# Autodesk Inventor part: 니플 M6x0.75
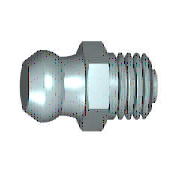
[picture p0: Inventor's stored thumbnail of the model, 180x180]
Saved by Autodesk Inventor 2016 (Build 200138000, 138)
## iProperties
IsCustomPart: 1
Created: 2012-02
Part Number: 니플 M6x0.75
Material: 강철, 연강
Description: 윤활 니플, 원추 유형 A
Document SubType Name: Modeling
Standard: JIS B 1575
Designer: mduedu
Standards Organization: JIS
Language: ko-KR
Size Designation: MT 6 x 0.75
Categories: <MemberInstance><Categories><Category DisplayName="기타 부품" InternalName="5aa15e00-363f-49f2-933f-16f664388e3f" Mnemonic="OTHER"><Category DisplayName="그리스 부속품" I
Density: 1 g/cm^3
Appearance: 강철
Author: mduedu
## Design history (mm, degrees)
sketch "스케치1"
  geometry: L1 (-8.8, 0)-(-8.8, 2.4); L2 (-8.8, 2.4)-(-7.335, 3.202); L3 (-8.8, 0)-(4.7, 0); L4 (4.7, 0)-(4.7, 1.5); L5 (4.7, 1.5)-(4, 1.5); L6 (4, 1.5)-(4, 3); L7 (4, 3)-(0, 3); L8 (-11.5, 0)-(7.4, 0) reference; L9 (0, -1.733)-(0, 10.398) reference; L10 (-3, 3.5)-(0, 3.5); L11 (0, 3.5)-(0, 3); A1 r 3.3 centre (-6.535, 0) between (-4.789, 2.8) and (-7.335, 3.202); A2 r 6 centre (-6.053, 8.665) between (-4.789, 2.8) and (-3, 3.5)
  constraints: 18 end point, 5 perpendicular, 4 point on circle, 2 centre point, 2 parallel, 2 point on line, 1 collinear, 1 vertical
  dimensions: "d0" = 13.5 distance between parallel lines of L1 L4 (= GL); "d1" = 5.6 diameter of A1.start L3 (= KGB2); "d2" = 0.7 distance between parallel lines of L4 L6 (= PHH); "d3" = 3 diameter of L5 L3 (= 0.5 x NND); "d4" = 6 diameter of L7 L3 (= NND); "d5" = 6.6 dimension on A1 L3 (= KR); "d6" = 4.8 diameter of L1.end L3 (= KGB1); "d7" = 6 radius of A2 (= RBN); "d11" = 7 diameter of L10.start L3 (= SW); "d14" = 3 distance of L10.start L10.end (= KOH); "d15" = 4 distance between parallel lines of L6 L11 (= NLG); "d61" = 7.33505 distance from line of L9 L2.end (computed from KGB1, KR, PHH, GL, NLG, VERS); "d62" = 6.53505 distance from line of L9 A1.centre (computed from NLG, GL, PHH, KR, KGB1)
revolve "본체" sketch "스케치1" stored, may be unused: angle "d25" = 90 deg
sketch "스케치2"
  geometry: L1 (2.021, 3.5)-(4.041, 0); L2 (4.041, 0)-(2.021, -3.5); L3 (2.021, -3.5)-(-2.021, -3.5); L4 (-2.021, -3.5)-(-4.041, 0); L5 (-4.041, 0)-(-2.021, 3.5); L6 (-2.021, 3.5)-(2.021, 3.5); C1 r 3.5 at (0, 0) reference; 1 further point
  constraints: 12 end point, 1 coincident, 1 horizontal, 1 tangent, 11 other
extrude "머리" join sketch "스케치2" distance "d17" = 3 (= KOH); taper "d18" = 0 deg
sketch "스케치3"
  geometry: L1 (2.687, 4.041)-(3, 4.041); L2 (3, 4.041)-(3, 3.5); L3 (3, 3.5)-(2.687, 4.041); L4 (0.313, 4.041)-(0, 4.041); L5 (0, 4.041)-(0, 3.5); L6 (0, 3.5)-(0.313, 4.041); L7 (3.6, 0)-(-0.6, 0) reference; L8 (0, 4.041)-(0, 2.021) reference; L9 (0, 4.041)-(3, 4.041) reference; L10 (3, 3.031)-(3, 4.041) reference
  constraints: 12 end point, 4 collinear, 3 perpendicular, 1 horizontal
  dimensions: "d19" = 3.5 distance from line of L5.end L7 (= 0.5 x SW); "d20" = 3.5 distance from line of L2.end L7 (= 0.5 x SW); "d21" = 30 deg angle of L6 L5; "d22" = 30 deg angle of L2 L3
revolve "모따기1" sketch "스케치3" stored, may be unused: angle "d56" = 90 deg
body "Solid1"
fillet "모깎기1" dims "d8" = 0.2 (= RR)
feature "스레드1" dims "d9" = 3.53991 (= NLG - GAL), "d10" = 0
chamfer "모따기2" distance "d23" = 0.46009 (= -0.5 x GD1 + 0.5 x NND); stored, may be unused: angle "d24" = 45 deg, second distance "d59" = 0.46009 (= -0.5 x GD1 + 0.5 x NND)
other parameters: "NLG" = 4 [user parameter; used in 4 equation terms], "GL" = 13.5 [user parameter; used in 3 equation terms], "NND" = 6 [user parameter; used in 4 equation terms], "KGB1" = 4.8 [user parameter; used in 3 equation terms], "KGB2" = 5.6 [user parameter; used in 1 equation term], "VERS" = 0.8 [user parameter; used in 1 equation term], "KR" = 6.6 [user parameter; used in 3 equation terms], "RBN" = 6 [user parameter; used in 1 equation term], "SW" = 7 [user parameter; used in 3 equation terms], "KOH" = 3 [user parameter; used in 2 equation terms], "GAL" = 0.46009 (= 0.61345 x PTC) [user parameter; used in 1 equation term], "FAWI" = 45 deg [user parameter], "PHH" = 0.7 [user parameter; used in 3 equation terms], "GD1" = 5.07983 (= THREADDIA - 1.2269 x PTC) [user parameter; used in 2 equation terms], "RR" = 0.2 [user parameter; used in 1 equation term], "d12" = 0, "d13" = 0, "GUL" = 0.46009 (= 0.61345 x PTC) [user parameter], "TPU" = 13.33333 (computed from PTC) [user parameter], "DULO" = 1.5 [user parameter], "PTC" = 0.75 [user parameter; used in 4 equation terms], "GEL" = 4 [user parameter], "THREADDIA" = 6 [user parameter; used in 1 equation term], "TOA" = 30 deg [user parameter]
